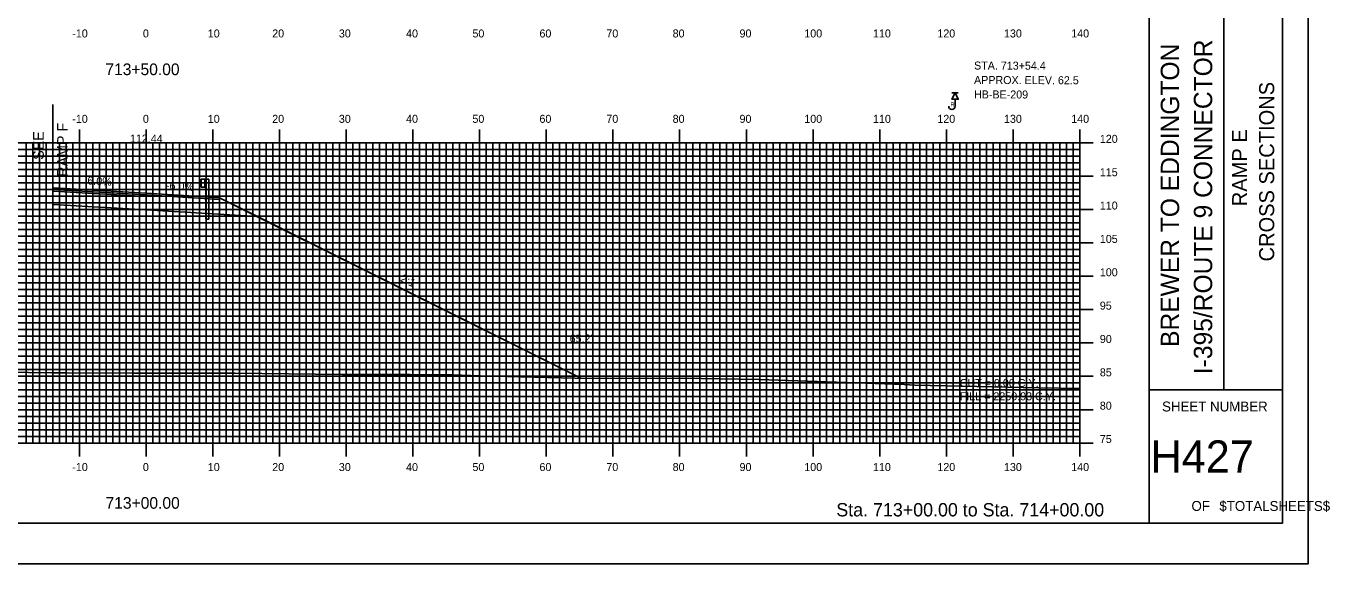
# Model space of a CAD drawing. Extents: x 855690 to 856034, y 364366 to 364586.
# Drawn here: x 855838.3 to 856033.8, y 364365.7 to 364446.3 of the extents above; entities that cross this region are included whole.
import ezdxf

# ---------------------------------------------------------------- set-up
doc = ezdxf.new("R2010")
doc.units = 0
for name, color, linetype in [('ANNOTATION', 7, 'Continuous'), ('BORDER', 7, 'Continuous'), ('BORING - REFUSAL', 7, 'Continuous'), ('D_Guardrail_Beam_Rt', 7, 'Continuous'), ('D_Roadway_Centerline', 7, 'Continuous'), ('D_Roadway_Centerline_Text', 7, 'Continuous'), ('D_Roadway_Edge_Shoulder', 7, 'Continuous'), ('D_Roadway_Edge_TW', 7, 'Continuous'), ('D_Roadway_Pavement', 7, 'Continuous'), ('D_Roadway_SlopeLines', 7, 'Continuous'), ('D_Roadway_SubGrade', 7, 'Continuous'), ('D_Text_Standard', 7, 'Continuous'), ('H_V ANNOTATION', 7, 'Continuous'), ('MAJOR', 7, 'Continuous'), ('MINOR', 7, 'Continuous'), ('PLOT BOUNDARY', 7, 'Continuous'), ('S_Roadway_Centerline', 7, 'Continuous')]:
    doc.layers.add(name, color=color, linetype=linetype)

msp = doc.modelspace()

# ---------------------------------------------------------------- linework, layer by layer
at = {"layer": 'BORDER'}
for p, q in [((856006.68, 364371.79), (856006.68, 364581.79)), ((856017.87, 364391.79), (856017.87, 364461.79)), ((856006.68, 364391.79), (856026.68, 364391.79))]:
    msp.add_line(p, q, dxfattribs=at)
msp.add_lwpolyline([(855706.68, 364371.79), (856026.68, 364371.79), (856026.68, 364581.79), (855706.68, 364581.79)], close=True, dxfattribs=at)
at = {"layer": 'BORING - REFUSAL'}
for p, q in [((855978.06, 364436.29), (855977.1, 364436.29)), ((855977.58, 364435.33), (855977.58, 364434.27))]:
    msp.add_line(p, q, dxfattribs=at)
msp.add_lwpolyline([(855977.58, 364436.29), (855978.06, 364435.33), (855977.1, 364435.33)], close=True, dxfattribs=at)
msp.add_arc((855977.1, 364434.27), 0.485, 180, 0, dxfattribs=at)
at = {"layer": 'D_Guardrail_Beam_Rt'}
for p, q in [((855864.46, 364423.23), (855864.32, 364423.13)), ((855864.32, 364422.98), (855864.52, 364422.85)), ((855864.52, 364422.65), (855864.32, 364422.51)), ((855864.32, 364422.37), (855864.46, 364422.27)), ((855864.55, 364423.25), (855864.48, 364423.23)), ((855864.55, 364423.33), (855865.24, 364423.33)), ((855864.55, 364422.16), (855864.55, 364423.33)), ((855864.55, 364422.78), (855864.55, 364422.71)), ((855865.07, 364423.33), (855865.07, 364422.16)), ((855865.18, 364423.33), (855865.18, 364422.16)), ((855865.24, 364423.33), (855865.71, 364423.33)), ((855865.24, 364423.33), (855865.24, 364422.16)), ((855865.71, 364423.33), (855865.71, 364417.33)), ((855864.48, 364422.26), (855864.55, 364422.25)), ((855865.24, 364422.16), (855864.55, 364422.16)), ((855865.22, 364417.33), (855865.22, 364422.16)), ((855865.22, 364417.33), (855865.71, 364417.33))]:
    msp.add_line(p, q, dxfattribs=at)
for centre, major_axis, start_param, end_param in [((855864.37, 364423.05), (-0.0877, 0), 5.323254, 7.243116), ((855864.37, 364422.44), (-0.0877, 0), 5.323254, 7.243116), ((855864.49, 364423.19), (-0.0417, 0), 4.907132, 5.323254), ((855864.47, 364422.78), (0.0789, 0), 0, 0.959931), ((855864.47, 364422.71), (0.0789, 0), 5.323254, 6.283185), ((855864.49, 364422.3), (-0.0417, 0), 0.959931, 1.376053)]:
    msp.add_ellipse(centre, major_axis=major_axis, ratio=0.995501, start_param=start_param, end_param=end_param, dxfattribs=at)
at = {"layer": 'D_Roadway_Centerline'}
msp.add_lwpolyline([(855842.28, 364422.07), (855856.28, 364421.23), (855864.28, 364420.75), (855867.28, 364420.57), (855872.96, 364417.73), (855921.44, 364393.49)], dxfattribs=at)
at = {"layer": 'D_Roadway_Edge_Shoulder'}
msp.add_lwpolyline([(855856.28, 364421.23), (855864.28, 364420.75), (855864.28, 364420.75), (855867.28, 364420.57), (855867.28, 364420.32), (855856.28, 364420.98)], close=True, dxfattribs=at)
at = {"layer": 'D_Roadway_Edge_TW'}
msp.add_lwpolyline([(855842.28, 364422.07), (855856.28, 364421.23), (855856.28, 364420.98), (855842.28, 364421.82)], close=True, dxfattribs=at)
at = {"layer": 'D_Roadway_Pavement'}
msp.add_lwpolyline([(855842.28, 364421.82), (855856.28, 364420.98), (855856.28, 364420.73), (855842.28, 364421.57)], close=True, dxfattribs=at)
msp.add_lwpolyline([(855856.28, 364420.98), (855856.28, 364420.73)], dxfattribs=at)
msp.add_lwpolyline([(855856.28, 364420.98), (855856.28, 364420.73)], dxfattribs=at)
at = {"layer": 'D_Roadway_SlopeLines'}
msp.add_lwpolyline([(855867.28, 364420.57), (855921.44, 364393.49)], dxfattribs=at)
at = {"layer": 'D_Roadway_SubGrade'}
msp.add_line((855842.28, 364434.52), (855842.28, 364419.57), dxfattribs=at)
for points in [[(855842.28, 364421.57), (855856.28, 364420.73), (855856.28, 364418.73), (855842.28, 364419.57)], [(855856.28, 364420.73), (855856.28, 364420.98), (855867.28, 364420.32), (855867.28, 364420.57), (855872.96, 364417.73), (855856.28, 364418.73)]]:
    msp.add_lwpolyline(points, close=True, dxfattribs=at)
at = {"layer": 'MAJOR'}
for p, q in [((855846.28, 364430.79), (855846.28, 364428.79)), ((855856.28, 364430.79), (855856.28, 364428.79)), ((855866.28, 364430.79), (855866.28, 364428.79)), ((855876.28, 364430.79), (855876.28, 364428.79)), ((855886.28, 364430.79), (855886.28, 364428.79)), ((855896.28, 364430.79), (855896.28, 364428.79)), ((855906.28, 364430.79), (855906.28, 364428.79)), ((855916.28, 364430.79), (855916.28, 364428.79)), ((855926.28, 364430.79), (855926.28, 364428.79)), ((855936.28, 364430.79), (855936.28, 364428.79)), ((855946.28, 364430.79), (855946.28, 364428.79)), ((855956.28, 364430.79), (855956.28, 364428.79)), ((855966.28, 364430.79), (855966.28, 364428.79)), ((855976.28, 364430.79), (855976.28, 364428.79)), ((855986.28, 364430.79), (855986.28, 364428.79)), ((855996.28, 364430.79), (855996.28, 364428.79)), ((855716.28, 364428.79), (855996.28, 364428.79)), ((855716.28, 364428.79), (855996.28, 364428.79)), ((855846.28, 364383.79), (855846.28, 364428.79)), ((855856.28, 364383.79), (855856.28, 364428.79)), ((855866.28, 364383.79), (855866.28, 364428.79)), ((855876.28, 364383.79), (855876.28, 364428.79)), ((855886.28, 364383.79), (855886.28, 364428.79)), ((855896.28, 364383.79), (855896.28, 364428.79)), ((855906.28, 364383.79), (855906.28, 364428.79)), ((855916.28, 364383.79), (855916.28, 364428.79)), ((855926.28, 364383.79), (855926.28, 364428.79)), ((855936.28, 364383.79), (855936.28, 364428.79)), ((855946.28, 364383.79), (855946.28, 364428.79)), ((855956.28, 364383.79), (855956.28, 364428.79)), ((855966.28, 364383.79), (855966.28, 364428.79)), ((855976.28, 364383.79), (855976.28, 364428.79)), ((855986.28, 364383.79), (855986.28, 364428.79)), ((855998.29, 364428.79), (855994.28, 364428.79)), ((855996.28, 364383.79), (855996.28, 364428.79)), ((855996.28, 364383.79), (855996.28, 364428.79)), ((855716.28, 364423.79), (855996.28, 364423.79)), ((855998.29, 364423.79), (855994.28, 364423.79)), ((855716.28, 364418.79), (855996.28, 364418.79)), ((855998.29, 364418.79), (855994.28, 364418.79)), ((855716.28, 364413.79), (855996.28, 364413.79)), ((855998.29, 364413.79), (855994.28, 364413.79)), ((855716.28, 364408.79), (855996.28, 364408.79)), ((855998.29, 364408.79), (855994.28, 364408.79)), ((855716.28, 364403.79), (855996.28, 364403.79)), ((855998.29, 364403.79), (855994.28, 364403.79)), ((855716.28, 364398.79), (855996.28, 364398.79)), ((855998.29, 364398.79), (855994.28, 364398.79)), ((855716.28, 364393.79), (855996.28, 364393.79)), ((855998.29, 364393.79), (855994.28, 364393.79)), ((855716.28, 364388.79), (855996.28, 364388.79)), ((855998.29, 364388.79), (855994.28, 364388.79)), ((855716.28, 364383.79), (855996.28, 364383.79)), ((855716.28, 364383.79), (855996.28, 364383.79)), ((855846.28, 364381.78), (855846.28, 364383.79)), ((855856.28, 364381.78), (855856.28, 364383.79)), ((855866.28, 364381.78), (855866.28, 364383.79)), ((855876.28, 364381.78), (855876.28, 364383.79)), ((855886.28, 364381.78), (855886.28, 364383.79)), ((855896.28, 364381.78), (855896.28, 364383.79)), ((855906.28, 364381.78), (855906.28, 364383.79)), ((855916.28, 364381.78), (855916.28, 364383.79)), ((855926.28, 364381.78), (855926.28, 364383.79)), ((855936.28, 364381.78), (855936.28, 364383.79)), ((855946.28, 364381.78), (855946.28, 364383.79)), ((855956.28, 364381.78), (855956.28, 364383.79)), ((855966.28, 364381.78), (855966.28, 364383.79)), ((855976.28, 364381.78), (855976.28, 364383.79)), ((855986.28, 364381.78), (855986.28, 364383.79)), ((855998.29, 364383.79), (855994.28, 364383.79)), ((855996.28, 364381.78), (855996.28, 364383.79))]:
    msp.add_line(p, q, dxfattribs=at)
at = {"layer": 'MINOR'}
for p, q in [((855838.28, 364383.79), (855838.28, 364428.79)), ((855839.28, 364383.79), (855839.28, 364428.79)), ((855840.28, 364383.79), (855840.28, 364428.79)), ((855841.28, 364383.79), (855841.28, 364428.79)), ((855842.28, 364383.79), (855842.28, 364428.79)), ((855843.28, 364383.79), (855843.28, 364428.79)), ((855844.28, 364383.79), (855844.28, 364428.79)), ((855845.28, 364383.79), (855845.28, 364428.79)), ((855847.28, 364383.79), (855847.28, 364428.79)), ((855848.28, 364383.79), (855848.28, 364428.79)), ((855849.28, 364383.79), (855849.28, 364428.79)), ((855850.28, 364383.79), (855850.28, 364428.79)), ((855851.28, 364383.79), (855851.28, 364428.79)), ((855852.28, 364383.79), (855852.28, 364428.79)), ((855853.28, 364383.79), (855853.28, 364428.79)), ((855854.28, 364383.79), (855854.28, 364428.79)), ((855855.28, 364383.79), (855855.28, 364428.79)), ((855857.28, 364383.79), (855857.28, 364428.79)), ((855858.28, 364383.79), (855858.28, 364428.79)), ((855859.28, 364383.79), (855859.28, 364428.79)), ((855860.28, 364383.79), (855860.28, 364428.79)), ((855861.28, 364383.79), (855861.28, 364428.79)), ((855862.28, 364383.79), (855862.28, 364428.79)), ((855863.28, 364383.79), (855863.28, 364428.79)), ((855864.28, 364383.79), (855864.28, 364428.79)), ((855865.28, 364383.79), (855865.28, 364428.79)), ((855867.28, 364383.79), (855867.28, 364428.79)), ((855868.28, 364383.79), (855868.28, 364428.79)), ((855869.28, 364383.79), (855869.28, 364428.79)), ((855870.28, 364383.79), (855870.28, 364428.79)), ((855871.28, 364383.79), (855871.28, 364428.79)), ((855872.28, 364383.79), (855872.28, 364428.79)), ((855873.28, 364383.79), (855873.28, 364428.79)), ((855874.28, 364383.79), (855874.28, 364428.79)), ((855875.28, 364383.79), (855875.28, 364428.79)), ((855877.28, 364383.79), (855877.28, 364428.79)), ((855878.28, 364383.79), (855878.28, 364428.79)), ((855879.28, 364383.79), (855879.28, 364428.79)), ((855880.28, 364383.79), (855880.28, 364428.79)), ((855881.28, 364383.79), (855881.28, 364428.79)), ((855882.28, 364383.79), (855882.28, 364428.79)), ((855883.28, 364383.79), (855883.28, 364428.79)), ((855884.28, 364383.79), (855884.28, 364428.79)), ((855885.28, 364383.79), (855885.28, 364428.79)), ((855887.28, 364383.79), (855887.28, 364428.79)), ((855888.28, 364383.79), (855888.28, 364428.79)), ((855889.28, 364383.79), (855889.28, 364428.79)), ((855890.28, 364383.79), (855890.28, 364428.79)), ((855891.28, 364383.79), (855891.28, 364428.79)), ((855892.28, 364383.79), (855892.28, 364428.79)), ((855893.28, 364383.79), (855893.28, 364428.79)), ((855894.28, 364383.79), (855894.28, 364428.79)), ((855895.28, 364383.79), (855895.28, 364428.79)), ((855897.28, 364383.79), (855897.28, 364428.79)), ((855898.28, 364383.79), (855898.28, 364428.79)), ((855899.28, 364383.79), (855899.28, 364428.79)), ((855900.28, 364383.79), (855900.28, 364428.79)), ((855901.28, 364383.79), (855901.28, 364428.79)), ((855902.28, 364383.79), (855902.28, 364428.79)), ((855903.28, 364383.79), (855903.28, 364428.79)), ((855904.28, 364383.79), (855904.28, 364428.79)), ((855905.28, 364383.79), (855905.28, 364428.79)), ((855907.28, 364383.79), (855907.28, 364428.79)), ((855908.28, 364383.79), (855908.28, 364428.79)), ((855909.28, 364383.79), (855909.28, 364428.79)), ((855910.28, 364383.79), (855910.28, 364428.79)), ((855911.28, 364383.79), (855911.28, 364428.79)), ((855912.28, 364383.79), (855912.28, 364428.79)), ((855913.28, 364383.79), (855913.28, 364428.79)), ((855914.28, 364383.79), (855914.28, 364428.79)), ((855915.28, 364383.79), (855915.28, 364428.79)), ((855917.28, 364383.79), (855917.28, 364428.79)), ((855918.28, 364383.79), (855918.28, 364428.79)), ((855919.28, 364383.79), (855919.28, 364428.79)), ((855920.28, 364383.79), (855920.28, 364428.79)), ((855921.28, 364383.79), (855921.28, 364428.79)), ((855922.28, 364383.79), (855922.28, 364428.79)), ((855923.28, 364383.79), (855923.28, 364428.79)), ((855924.28, 364383.79), (855924.28, 364428.79)), ((855925.28, 364383.79), (855925.28, 364428.79)), ((855927.28, 364383.79), (855927.28, 364428.79)), ((855928.28, 364383.79), (855928.28, 364428.79)), ((855929.28, 364383.79), (855929.28, 364428.79)), ((855930.28, 364383.79), (855930.28, 364428.79)), ((855931.28, 364383.79), (855931.28, 364428.79)), ((855932.28, 364383.79), (855932.28, 364428.79)), ((855933.28, 364383.79), (855933.28, 364428.79)), ((855934.28, 364383.79), (855934.28, 364428.79)), ((855935.28, 364383.79), (855935.28, 364428.79)), ((855937.28, 364383.79), (855937.28, 364428.79)), ((855938.28, 364383.79), (855938.28, 364428.79)), ((855939.28, 364383.79), (855939.28, 364428.79)), ((855940.28, 364383.79), (855940.28, 364428.79)), ((855941.28, 364383.79), (855941.28, 364428.79)), ((855942.28, 364383.79), (855942.28, 364428.79)), ((855943.28, 364383.79), (855943.28, 364428.79)), ((855944.28, 364383.79), (855944.28, 364428.79)), ((855945.28, 364383.79), (855945.28, 364428.79)), ((855947.28, 364383.79), (855947.28, 364428.79)), ((855948.28, 364383.79), (855948.28, 364428.79)), ((855949.28, 364383.79), (855949.28, 364428.79)), ((855950.28, 364383.79), (855950.28, 364428.79)), ((855951.28, 364383.79), (855951.28, 364428.79)), ((855952.28, 364383.79), (855952.28, 364428.79)), ((855953.28, 364383.79), (855953.28, 364428.79)), ((855954.28, 364383.79), (855954.28, 364428.79)), ((855955.28, 364383.79), (855955.28, 364428.79)), ((855957.28, 364383.79), (855957.28, 364428.79)), ((855958.28, 364383.79), (855958.28, 364428.79)), ((855959.28, 364383.79), (855959.28, 364428.79)), ((855960.28, 364383.79), (855960.28, 364428.79)), ((855961.28, 364383.79), (855961.28, 364428.79)), ((855962.28, 364383.79), (855962.28, 364428.79)), ((855963.28, 364383.79), (855963.28, 364428.79)), ((855964.28, 364383.79), (855964.28, 364428.79)), ((855965.28, 364383.79), (855965.28, 364428.79)), ((855967.28, 364383.79), (855967.28, 364428.79)), ((855968.28, 364383.79), (855968.28, 364428.79)), ((855969.28, 364383.79), (855969.28, 364428.79)), ((855970.28, 364383.79), (855970.28, 364428.79)), ((855971.28, 364383.79), (855971.28, 364428.79)), ((855972.28, 364383.79), (855972.28, 364428.79)), ((855973.28, 364383.79), (855973.28, 364428.79)), ((855974.28, 364383.79), (855974.28, 364428.79)), ((855975.28, 364383.79), (855975.28, 364428.79)), ((855977.28, 364383.79), (855977.28, 364428.79)), ((855978.28, 364383.79), (855978.28, 364428.79)), ((855979.28, 364383.79), (855979.28, 364428.79)), ((855980.28, 364383.79), (855980.28, 364428.79)), ((855981.28, 364383.79), (855981.28, 364428.79)), ((855982.28, 364383.79), (855982.28, 364428.79)), ((855983.28, 364383.79), (855983.28, 364428.79)), ((855984.28, 364383.79), (855984.28, 364428.79)), ((855985.28, 364383.79), (855985.28, 364428.79)), ((855987.28, 364383.79), (855987.28, 364428.79)), ((855988.28, 364383.79), (855988.28, 364428.79)), ((855989.28, 364383.79), (855989.28, 364428.79)), ((855990.28, 364383.79), (855990.28, 364428.79)), ((855991.28, 364383.79), (855991.28, 364428.79)), ((855992.28, 364383.79), (855992.28, 364428.79)), ((855993.28, 364383.79), (855993.28, 364428.79)), ((855994.28, 364383.79), (855994.28, 364428.79)), ((855995.28, 364383.79), (855995.28, 364428.79)), ((855716.28, 364427.79), (855996.28, 364427.79)), ((855716.28, 364426.79), (855996.28, 364426.79)), ((855996.28, 364427.79), (855994.28, 364427.79)), ((855996.28, 364426.79), (855994.28, 364426.79)), ((855716.28, 364425.79), (855996.28, 364425.79)), ((855716.28, 364424.79), (855996.28, 364424.79)), ((855996.28, 364425.79), (855994.28, 364425.79)), ((855996.28, 364424.79), (855994.28, 364424.79)), ((855716.28, 364422.79), (855996.28, 364422.79)), ((855996.28, 364422.79), (855994.28, 364422.79)), ((855716.28, 364421.79), (855996.28, 364421.79)), ((855716.28, 364420.79), (855996.28, 364420.79)), ((855996.28, 364421.79), (855994.28, 364421.79)), ((855996.28, 364420.79), (855994.28, 364420.79)), ((855716.28, 364419.79), (855996.28, 364419.79)), ((855996.28, 364419.79), (855994.28, 364419.79)), ((855716.28, 364417.79), (855996.28, 364417.79)), ((855716.28, 364416.79), (855996.28, 364416.79)), ((855996.28, 364417.79), (855994.28, 364417.79)), ((855996.28, 364416.79), (855994.28, 364416.79)), ((855716.28, 364415.79), (855996.28, 364415.79)), ((855716.28, 364414.79), (855996.28, 364414.79)), ((855996.28, 364415.79), (855994.28, 364415.79)), ((855996.28, 364414.79), (855994.28, 364414.79)), ((855716.28, 364412.79), (855996.28, 364412.79)), ((855996.28, 364412.79), (855994.28, 364412.79)), ((855716.28, 364411.79), (855996.28, 364411.79)), ((855716.28, 364410.79), (855996.28, 364410.79)), ((855996.28, 364411.79), (855994.28, 364411.79)), ((855996.28, 364410.79), (855994.28, 364410.79)), ((855716.28, 364409.79), (855996.28, 364409.79)), ((855996.28, 364409.79), (855994.28, 364409.79)), ((855716.28, 364407.79), (855996.28, 364407.79)), ((855716.28, 364406.79), (855996.28, 364406.79)), ((855996.28, 364407.79), (855994.28, 364407.79)), ((855996.28, 364406.79), (855994.28, 364406.79)), ((855716.28, 364405.79), (855996.28, 364405.79)), ((855716.28, 364404.79), (855996.28, 364404.79)), ((855996.28, 364405.79), (855994.28, 364405.79)), ((855996.28, 364404.79), (855994.28, 364404.79)), ((855716.28, 364402.79), (855996.28, 364402.79)), ((855996.28, 364402.79), (855994.28, 364402.79)), ((855716.28, 364401.79), (855996.28, 364401.79)), ((855716.28, 364400.79), (855996.28, 364400.79)), ((855996.28, 364401.79), (855994.28, 364401.79)), ((855996.28, 364400.79), (855994.28, 364400.79)), ((855716.28, 364399.79), (855996.28, 364399.79)), ((855996.28, 364399.79), (855994.28, 364399.79)), ((855716.28, 364397.79), (855996.28, 364397.79)), ((855996.28, 364397.79), (855994.28, 364397.79)), ((855716.28, 364396.79), (855996.28, 364396.79)), ((855716.28, 364395.79), (855996.28, 364395.79)), ((855996.28, 364396.79), (855994.28, 364396.79)), ((855996.28, 364395.79), (855994.28, 364395.79)), ((855716.28, 364394.79), (855996.28, 364394.79)), ((855996.28, 364394.79), (855994.28, 364394.79)), ((855716.28, 364392.79), (855996.28, 364392.79)), ((855716.28, 364391.79), (855996.28, 364391.79)), ((855996.28, 364392.79), (855994.28, 364392.79)), ((855996.28, 364391.79), (855994.28, 364391.79)), ((855716.28, 364390.79), (855996.28, 364390.79)), ((855716.28, 364389.79), (855996.28, 364389.79)), ((855996.28, 364390.79), (855994.28, 364390.79)), ((855996.28, 364389.79), (855994.28, 364389.79)), ((855716.28, 364387.79), (855996.28, 364387.79)), ((855996.28, 364387.79), (855994.28, 364387.79)), ((855716.28, 364386.79), (855996.28, 364386.79)), ((855716.28, 364385.79), (855996.28, 364385.79)), ((855996.28, 364386.79), (855994.28, 364386.79)), ((855996.28, 364385.79), (855994.28, 364385.79)), ((855716.28, 364384.79), (855996.28, 364384.79)), ((855996.28, 364384.79), (855994.28, 364384.79))]:
    msp.add_line(p, q, dxfattribs=at)
at = {"layer": 'PLOT BOUNDARY'}
msp.add_lwpolyline([(855690.5, 364365.67), (856030.5, 364365.67), (856030.5, 364585.67), (855690.5, 364585.67)], close=True, dxfattribs=at)
at = {"layer": 'S_Roadway_Centerline'}
msp.add_lwpolyline([(855831.57, 364394.47), (855842.14, 364394.32), (855844.14, 364394.29), (855854.5, 364394.28), (855864.9, 364394.28), (855866.88, 364394.24), (855869.58, 364394.24), (855885.72, 364394.06), (855895.87, 364394.04), (855902.12, 364393.99), (855906.41, 364393.85), (855920.58, 364393.49), (855927.54, 364393.47), (855936.7, 364393.52), (855948.14, 364393.29), (855948.37, 364393.29), (855949.67, 364393.24), (855969.95, 364392.55), (855971.56, 364392.48), (855973.85, 364392.41), (855990.15, 364392.08), (855996.28, 364391.97)], dxfattribs=at)

# ---------------------------------------------------------------- texts
at = {"layer": 'ANNOTATION'}
for s, height, rotation, p in [('SEE', 1.6, 90, (855840.94, 364426.25)), ('RAMP F', 1.6, 90, (855844.54, 364423.71)), ('6.0%', 1.2, 356.5664, (855847.44, 364422.56)), ('-6.0%', 1.2, 356.5664, (855859.23, 364421.83)), ('2:1', 1.2, 333.4349, (855894.3, 364408.1))]:
    msp.add_text(s, height=height, rotation=rotation, dxfattribs=at).set_placement(p)
at = {"layer": 'BORDER'}
for s, height, p in [('I-395/ROUTE 9 CONNECTOR', 2.7557, (856016.13, 364394.12)), ('BREWER TO EDDINGTON', 2.7557, (856011.17, 364398.2)), ('CROSS SECTIONS', 2.25, (856025.42, 364411.01)), ('RAMP E', 2.25, (856021.37, 364419.29))]:
    msp.add_text(s, height=height, rotation=90, dxfattribs=at).set_placement(p)
for s, height, p in [('SHEET NUMBER', 1.4905, (856008.61, 364388.52)), ('H427', 4.839, (856006.89, 364379.35)), ('OF', 1.491, (856013.02, 364373.61)), ('$TOTALSHEETS$', 1.4905, (856017.2, 364373.61))]:
    msp.add_text(s, height=height, dxfattribs=at).set_placement(p)
at = {"layer": 'BORING - REFUSAL'}
for s, p in [('STA. 713+54.4', (855980.42, 364439.78)), ('APPROX. ELEV. 62.5', (855980.42, 364437.62)), ('HB-BE-209', (855980.41, 364435.46))]:
    msp.add_text(s, height=1.2, rotation=359.8142, dxfattribs=at).set_placement(p)
msp.add_text('R', height=0.64, dxfattribs=at).set_placement((855976.87, 364434.21))
at = {"layer": 'D_Roadway_Centerline_Text'}
msp.add_text('112.44', height=1.2, dxfattribs=at).set_placement((855853.86, 364428.83))
at = {"layer": 'D_Text_Standard'}
for s, p in [("65.2'", (855919.79, 364398.86)), ('CUT = 0.00 C.Y.', (855978.28, 364392.19)), ('FILL = 2250.93 C.Y.', (855978.28, 364390.2))]:
    msp.add_text(s, height=1.2, dxfattribs=at).set_placement(p)
at = {"layer": 'H_V ANNOTATION'}
for s, height, p in [('-10', 1.2, (855845.21, 364444.59)), ('0', 1.2, (855855.8, 364444.59)), ('10', 1.2, (855865.53, 364444.59)), ('20', 1.2, (855875.19, 364444.59)), ('30', 1.2, (855885.18, 364444.59)), ('40', 1.2, (855895.26, 364444.59)), ('50', 1.2, (855905.21, 364444.59)), ('60', 1.2, (855915.26, 364444.59)), ('70', 1.2, (855925.29, 364444.59)), ('80', 1.2, (855935.23, 364444.59)), ('90', 1.2, (855945.26, 364444.59)), ('100', 1.2, (855954.97, 364444.59)), ('110', 1.2, (855965.27, 364444.59)), ('120', 1.2, (855974.92, 364444.59)), ('130', 1.2, (855984.91, 364444.59)), ('140', 1.2, (855994.99, 364444.59)), ('713+50.00', 1.75, (855850.17, 364438.94)), ('-10', 1.2, (855845.21, 364431.79)), ('0', 1.2, (855855.8, 364431.79)), ('10', 1.2, (855865.53, 364431.79)), ('20', 1.2, (855875.19, 364431.79)), ('30', 1.2, (855885.18, 364431.79)), ('40', 1.2, (855895.26, 364431.79)), ('50', 1.2, (855905.21, 364431.79)), ('60', 1.2, (855915.26, 364431.79)), ('70', 1.2, (855925.29, 364431.79)), ('80', 1.2, (855935.23, 364431.79)), ('90', 1.2, (855945.26, 364431.79)), ('100', 1.2, (855954.97, 364431.79)), ('110', 1.2, (855965.27, 364431.79)), ('120', 1.2, (855974.92, 364431.79)), ('130', 1.2, (855984.91, 364431.79)), ('140', 1.2, (855994.99, 364431.79)), ('120', 1.2, (855999.28, 364428.79)), ('115', 1.2, (855999.28, 364423.79)), ('110', 1.2, (855999.28, 364418.79)), ('105', 1.2, (855999.28, 364413.79)), ('100', 1.2, (855999.28, 364408.79)), ('95', 1.2, (855999.28, 364403.79)), ('90', 1.2, (855999.28, 364398.79)), ('85', 1.2, (855999.28, 364393.79)), ('80', 1.2, (855999.28, 364388.79)), ('75', 1.2, (855999.28, 364383.79)), ('-10', 1.2, (855845.21, 364379.59)), ('0', 1.2, (855855.8, 364379.59)), ('10', 1.2, (855865.53, 364379.59)), ('20', 1.2, (855875.19, 364379.59)), ('30', 1.2, (855885.18, 364379.59)), ('40', 1.2, (855895.26, 364379.59)), ('50', 1.2, (855905.21, 364379.59)), ('60', 1.2, (855915.26, 364379.59)), ('70', 1.2, (855925.29, 364379.59)), ('80', 1.2, (855935.23, 364379.59)), ('90', 1.2, (855945.26, 364379.59)), ('100', 1.2, (855954.97, 364379.59)), ('110', 1.2, (855965.27, 364379.59)), ('120', 1.2, (855974.92, 364379.59)), ('130', 1.2, (855984.91, 364379.59)), ('140', 1.2, (855994.99, 364379.59)), ('713+00.00', 1.75, (855850.2, 364373.94)), ('Sta. 713+00.00 to Sta. 714+00.00', 2.0004, (855959.77, 364372.79))]:
    msp.add_text(s, height=height, dxfattribs=at).set_placement(p)

doc.saveas('drawing.dxf')
